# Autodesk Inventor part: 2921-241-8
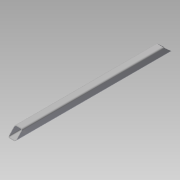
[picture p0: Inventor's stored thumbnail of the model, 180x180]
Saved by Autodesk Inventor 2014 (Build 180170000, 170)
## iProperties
Company: NHTSA/VRTC
Created: 2011-11
Part Number: 2921-241-8
Material: Steel
Document SubType Name: Modeling
Designer: Dave Walker
Density: 7.85 g/cm^3
Project: CHILD SIDE IMPACT SLED
Description: T.S. 2" x 2" x 1/8" x 1016mm (40.00")
Mass: 4248.83 g
Surface Area: 3425.37 cm^2
Volume: 541.252 cm^3
Stock Number: IMPACTOR FRAME TUBE 8
Appearance: Steel
Author: Dave Walker
Title: Impactor Frame Tube 8
Subject: Child Side Impact Sled
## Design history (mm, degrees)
node "Sketch1"
node "2921-105-81"
node "2921-105-8"
node "Base1"
